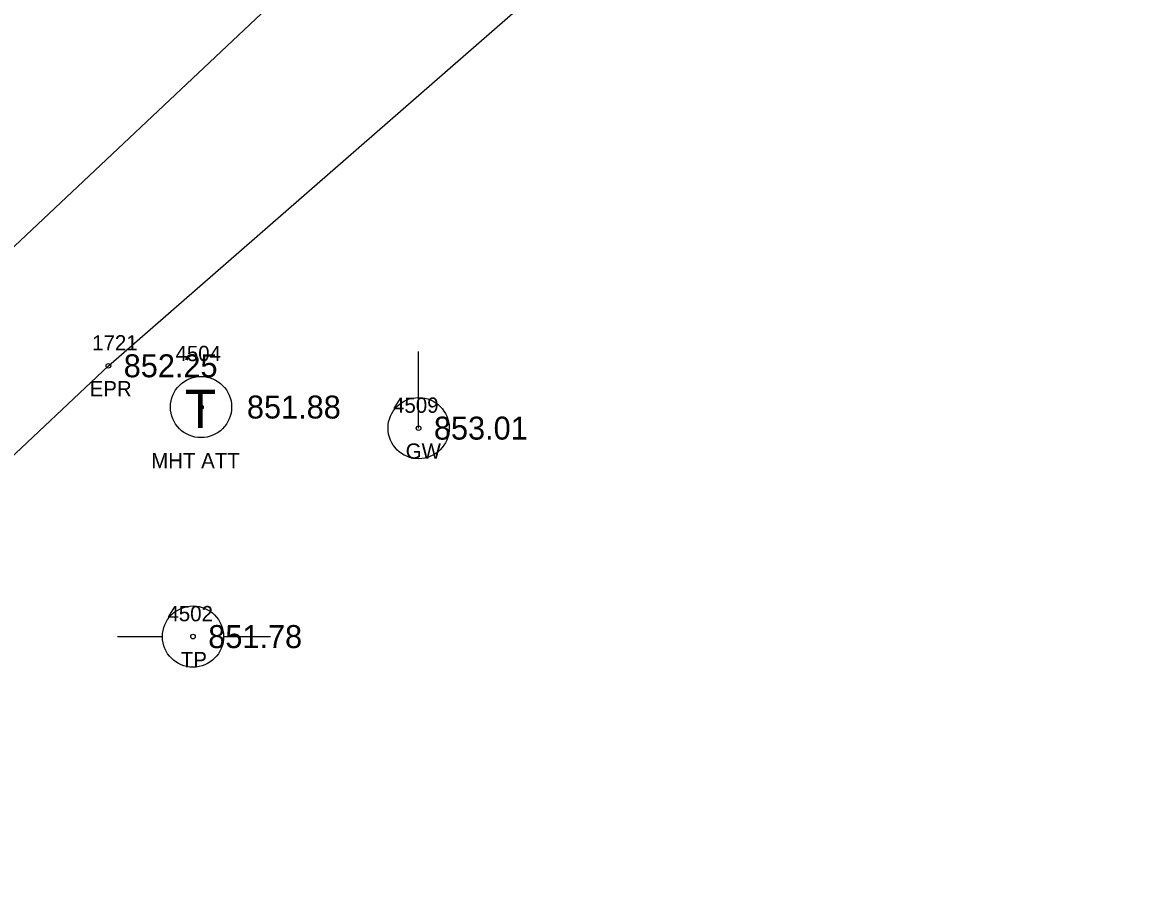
# Model space of a CAD drawing. Extents: x 1622501 to 1626664, y 1117816 to 1121579.
# Drawn here: x 1625022.1 to 1625095.7, y 1120185.2 to 1120242.5 of the extents above; entities that cross this region are included whole.
import ezdxf

# ---------------------------------------------------------------- set-up
doc = ezdxf.new("R2010")
doc.units = 0
for name, color, linetype in [('RD_EX_Road', 7, 'Continuous'), ('RD_EX_Road_txCode', 7, 'Continuous'), ('RD_EX_SU_Telecom', 7, 'Continuous'), ('RD_EX_TX_Road_ELEV', 7, 'Continuous'), ('RD_EX_TX_UT_ELEV', 7, 'Continuous'), ('RD_EX_UT', 7, 'Continuous'), ('RD_EX_UT_txCode', 7, 'Continuous'), ('RD_HC_Cl', 7, 'Continuous'), ('RD_SMD_Locator', 7, 'Continuous')]:
    doc.layers.add(name, color=color, linetype=linetype)

msp = doc.modelspace()

# ---------------------------------------------------------------- linework, layer by layer
at = {"layer": 'RD_EX_Road'}
msp.add_lwpolyline([(1624481.686, 1119706.573), (1624518.072, 1119740.622), (1624554.525, 1119774.632), (1624590.986, 1119808.778), (1624627.133, 1119843.173), (1624664.125, 1119876.781), (1624700.281, 1119911.275), (1624736.97, 1119945.679), (1624773.625, 1119979.796), (1624810.113, 1120014.451), (1624846.423, 1120048.907), (1624882.768, 1120083.191), (1624919.142, 1120117.136), (1624955.414, 1120151.754), (1624991.664, 1120186.106), (1625027.75, 1120220.093), (1625065.425, 1120252.962), (1625104.19, 1120284.121), (1625143.204, 1120315.036), (1625181.69, 1120345.902), (1625220.314, 1120377.13)], dxfattribs=at)
at = {"layer": 'RD_EX_SU_Telecom'}
msp.add_circle((1625033.805, 1120217.397), 2, dxfattribs=at)
at = {"layer": 'RD_EX_UT'}
for p, q in [((1625048.028, 1120216.02), (1625048.028, 1120221.02)), ((1625028.347, 1120202.414), (1625031.278, 1120202.414)), ((1625035.278, 1120202.414), (1625038.347, 1120202.414))]:
    msp.add_line(p, q, dxfattribs=at)
for centre, radius in [((1625048.028, 1120216.02), 1.999), ((1625033.278, 1120202.398), 2)]:
    msp.add_circle(centre, radius, dxfattribs=at)
at = {"layer": 'RD_HC_Cl'}
msp.add_line((1624870.491, 1120085.684), (1625124.669, 1120324.937), dxfattribs=at)
at = {"layer": 'RD_SMD_Locator'}
for centre in [(1625027.75, 1120220.093), (1625033.805, 1120217.397), (1625048.028, 1120216.02), (1625033.278, 1120202.398)]:
    msp.add_circle(centre, 0.15, dxfattribs=at)

# ---------------------------------------------------------------- texts
at = {"layer": 'RD_EX_Road_txCode'}
for s, p in [('1721', (1625026.687, 1120221.093)), ('EPR', (1625026.522, 1120218.093))]:
    msp.add_text(s, height=1, dxfattribs=at).set_placement(p)
at = {"layer": 'RD_EX_SU_Telecom'}
msp.add_text('T', height=2.5, dxfattribs=at).set_placement((1625032.744, 1120216.024))
at = {"layer": 'RD_EX_TX_Road_ELEV'}
msp.add_text('852.25', height=1.5, dxfattribs=at).set_placement((1625028.75, 1120219.343))
at = {"layer": 'RD_EX_TX_UT_ELEV'}
for s, p in [('851.88', (1625036.805, 1120216.647)), ('853.01', (1625049.028, 1120215.27)), ('851.78', (1625034.278, 1120201.648))]:
    msp.add_text(s, height=1.5, dxfattribs=at).set_placement(p)
at = {"layer": 'RD_EX_UT_txCode'}
for s, p in [('4504', (1625032.136, 1120220.397)), ('4509', (1625046.358, 1120217.02)), ('GW', (1625047.185, 1120214.02)), ('MHT ATT', (1625030.545, 1120213.397)), ('4502', (1625031.608, 1120203.398)), ('TP', (1625032.482, 1120200.398))]:
    msp.add_text(s, height=1, dxfattribs=at).set_placement(p)

doc.saveas('drawing.dxf')
